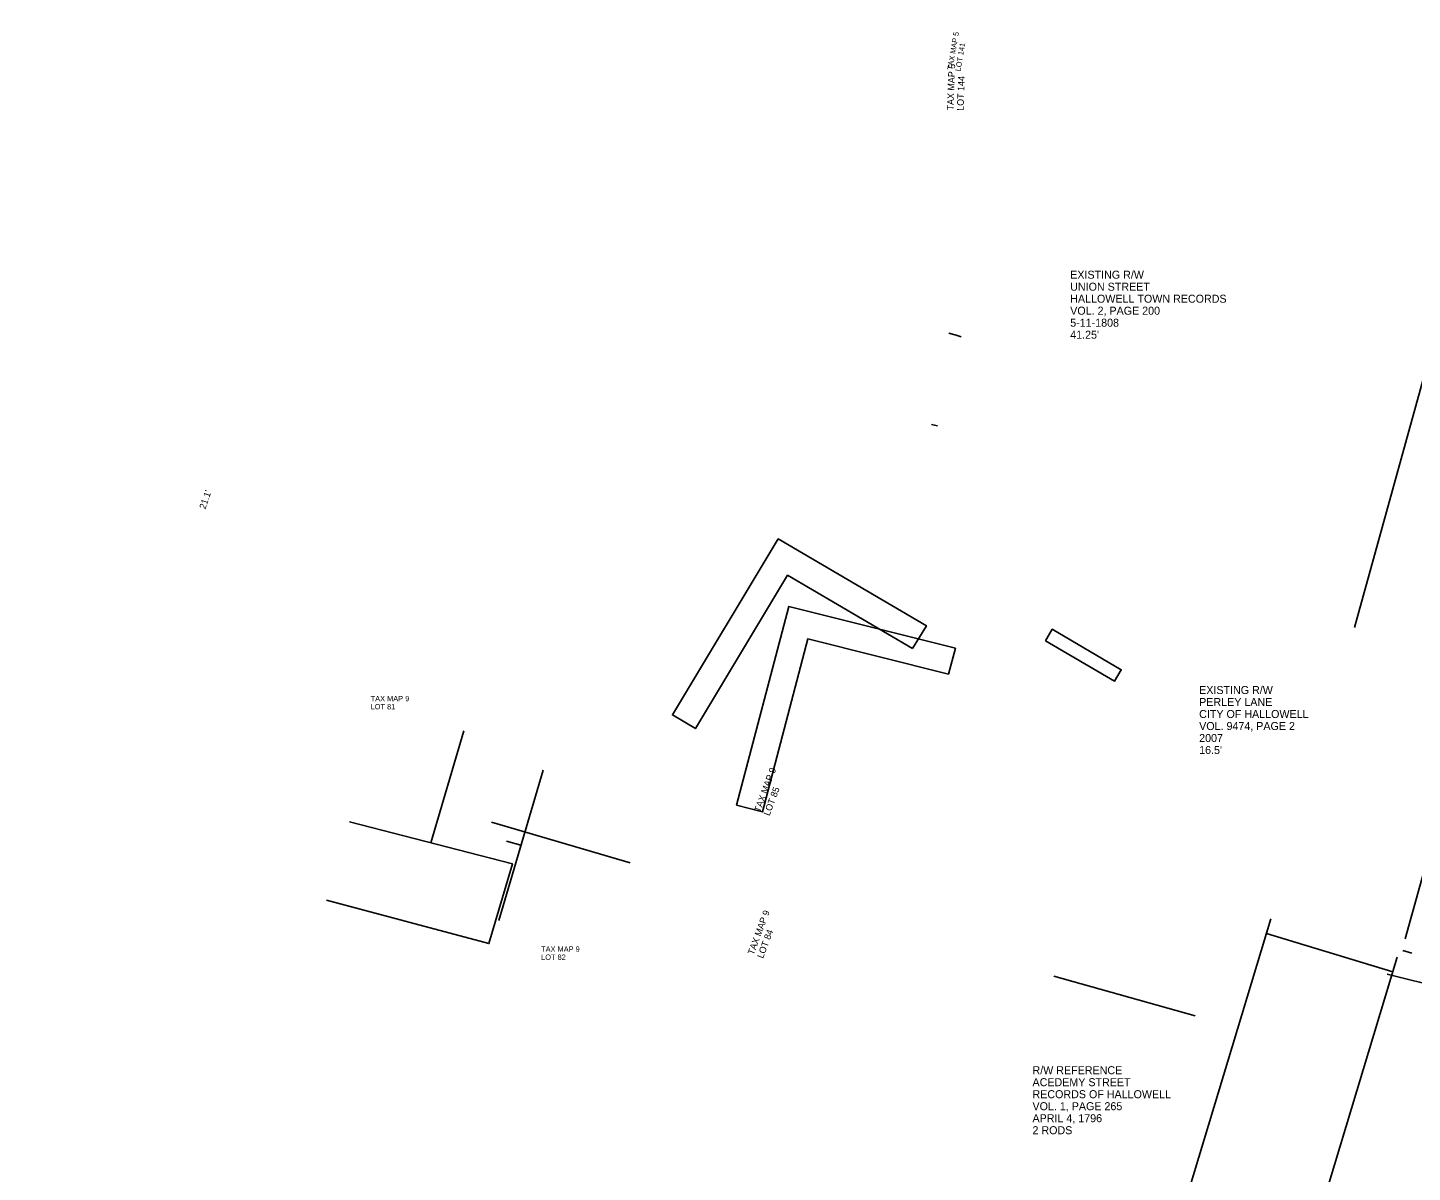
# Model space of a CAD drawing. Extents: x 1133267 to 1139526, y 528613 to 531538.
# Drawn here: x 1136530 to 1137049, y 529577 to 530006 of the extents above; entities that cross this region are included whole.
import ezdxf

# ---------------------------------------------------------------- set-up
doc = ezdxf.new("R2010")
doc.units = 0
for name, color, linetype in [('E_Property_Line', 7, 'Continuous'), ('E_Property_LotLine', 7, 'Continuous'), ('E_ROW_Line', 7, 'Continuous'), ('E_ROW_TieLine', 7, 'Continuous'), ('P_ROW_Tie_Lines', 7, 'Continuous'), ('PROPERTY NOTES', 7, 'Continuous'), ('ROW REFERENCES', 7, 'Continuous')]:
    doc.layers.add(name, color=color, linetype=linetype)

msp = doc.modelspace()

# ---------------------------------------------------------------- linework, layer by layer
at = {"layer": 'E_Property_Line'}
msp.add_line((1137265.64, 529594.14), (1137039.69, 529650.92), dxfattribs=at)
at = {"layer": 'E_Property_LotLine'}
msp.add_line((1136967.8, 529635.3), (1136914.76, 529650.21), dxfattribs=at)
at = {"layer": 'E_ROW_Line'}
for p, q in [((1137027.45, 529780.84), (1137103.47, 530055.63)), ((1137046.52, 529664.13), (1137086.27, 529807.81)), ((1136996.11, 529671.67), (1136878.13, 529281.57)), ((1137048.97, 529658.77), (1137045.61, 529659.75)), ((1137043.49, 529657.34), (1136925.63, 529267.65))]:
    msp.add_line(p, q, dxfattribs=at)
at = {"layer": 'E_ROW_TieLine'}
for p, q in [((1136877.67, 529890.53), (1136875.39, 529891.17)), ((1136880.02, 529889.87), (1136877.74, 529890.51)), ((1136871.21, 529856.44), (1136868.87, 529856.98)), ((1136704.01, 529707.95), (1136755.96, 529692.66)), ((1136709.54, 529700.83), (1136715.02, 529699.22)), ((1136994.45, 529666.16), (1137041.83, 529651.83))]:
    msp.add_line(p, q, dxfattribs=at)
for points in [[(1136861.83, 529772.96), (1136867.04, 529781.5), (1136811.48, 529814.08), (1136771.82, 529748.09), (1136780.4, 529742.97), (1136814.95, 529800.45)], [(1136875.26, 529763.39), (1136877.86, 529773.05), (1136815.38, 529788.7), (1136795.87, 529714.23), (1136805.55, 529711.72), (1136822.55, 529776.6)]]:
    msp.add_lwpolyline(points, close=True, dxfattribs=at)
for points in [[(1136681.27, 529700.16), (1136693.62, 529742.13)], [(1136706.74, 529671.06), (1136723.3, 529727.37)], [(1136642.09, 529678.66), (1136703.01, 529662.4), (1136711.8, 529692.28), (1136650.75, 529708.05)]]:
    msp.add_lwpolyline(points, dxfattribs=at)
msp.add_arc((1137113, 529244.92), 1119.71, 117.14906, 150.19906, dxfattribs=at)
at = {"layer": 'P_ROW_Tie_Lines'}
msp.add_lwpolyline([(1136911.6, 529775.91), (1136937.48, 529760.74), (1136940.05, 529765.02), (1136914.17, 529780.2)], close=True, dxfattribs=at)

# ---------------------------------------------------------------- texts
at = {"layer": 'PROPERTY NOTES'}
for s, height, rotation, p in [('TAX MAP 5', 2, 80.2613, (1136876.79, 529989.72)), ('LOT 141', 2, 80.2613, (1136879.77, 529989.21)), ('TAX MAP 5', 2.5, 87.9281, (1136877.18, 529974.64)), ('LOT 144', 2.5, 87.9281, (1136880.93, 529974.5)), ("21.1'", 2.49, 71.4521, (1136596.72, 529825.03)), ('TAX MAP 9', 2.5, 69.6118, (1136804.66, 529711.38)), ('LOT 85', 2.5, 69.6118, (1136808.18, 529710.07)), ('TAX MAP 9', 2.5, 69.6118, (1136802.27, 529657.94)), ('LOT 84', 2.5, 69.6118, (1136805.78, 529656.63))]:
    msp.add_text(s, height=height, rotation=rotation, dxfattribs=at).set_placement(p)
for s, p in [('TAX MAP 9', (1136658.66, 529753.2)), ('LOT 81', (1136658.66, 529750.17)), ('TAX MAP 9', (1136722.57, 529659.31)), ('LOT 82', (1136722.57, 529656.27))]:
    msp.add_text(s, height=2.008, dxfattribs=at).set_placement(p)
at = {"layer": 'ROW REFERENCES'}
for s, p in [('EXISTING R/W', (1136920.92, 529911.6)), ('UNION STREET', (1136920.92, 529907.1)), ('HALLOWELL TOWN RECORDS', (1136920.92, 529902.6)), ('VOL. 2, PAGE 200', (1136920.92, 529898.1)), ('5-11-1808', (1136920.92, 529893.6)), ("41.25'", (1136920.92, 529889.1)), ('EXISTING R/W', (1136969.26, 529755.93)), ('PERLEY LANE', (1136969.26, 529751.43)), ('CITY OF HALLOWELL', (1136969.26, 529746.93)), ('VOL. 9474, PAGE 2', (1136969.26, 529742.43)), ('2007', (1136969.26, 529737.93)), ("16.5'", (1136969.26, 529733.43)), ('R/W REFERENCE', (1136906.78, 529613.42)), ('ACEDEMY STREET', (1136906.78, 529608.92)), ('RECORDS OF HALLOWELL', (1136906.78, 529604.42)), ('VOL. 1, PAGE 265', (1136906.78, 529599.92)), ('APRIL 4, 1796', (1136906.78, 529595.42)), ('2 RODS', (1136906.78, 529590.92))]:
    msp.add_text(s, height=3, dxfattribs=at).set_placement(p)

doc.saveas('drawing.dxf')
